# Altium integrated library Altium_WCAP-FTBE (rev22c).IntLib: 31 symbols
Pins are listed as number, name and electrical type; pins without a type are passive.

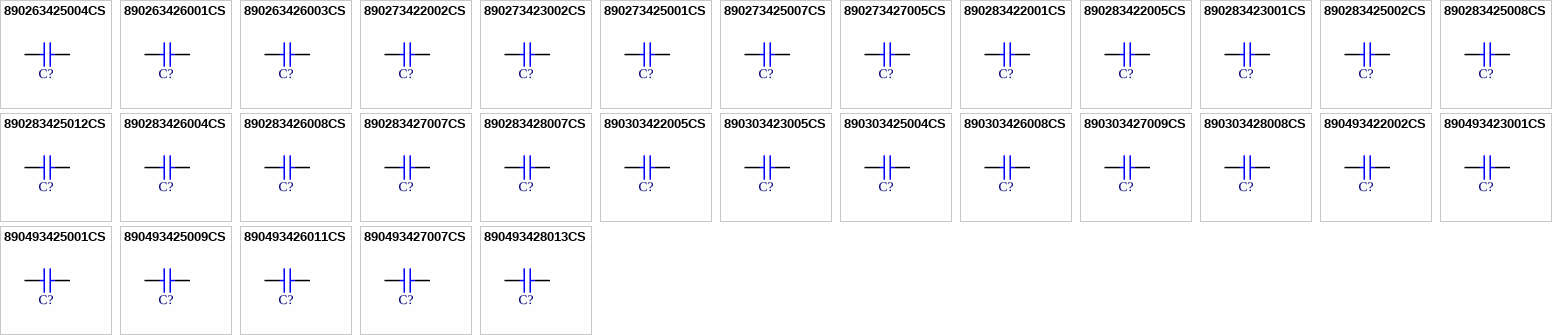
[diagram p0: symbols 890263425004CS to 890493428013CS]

## 890263425004CS
designator C?, comment 2.2µF  (value not drawn)
WCAP-FTBE Film Capacitor, THT, L18 x W8.5 x H15mm, 2.2µF, 100V; Manufacturer Part Number: 890263425004CS; Manufacturer: Wurth Elektronik; Capacitance Tolerance: +/-10%; Dissipation Factor @1kHz: 1%; Dissipation Factor @10kHz: 1.6%; Dissipation Factor @100kHz: 5%; Insulation Resistance: 3000Ω x F; Pitch: 15mm; Rate of Voltage Rise: 9V/µs; Technical Reference: MPSP015225K100DCPP45004
footprint WCAP-FTBE_L18W8.5H15
simulation model 890263425004CS_2.2uF
pins: 1, 2

## 890263426001CS
designator C?, comment 2.2µF  (value not drawn)
WCAP-FTBE Film Capacitor, THT, L26 x W6 x H15mm, 2.2µF, 100V; Manufacturer Part Number: 890263426001CS; Manufacturer: Wurth Elektronik; Capacitance Tolerance: +/-10%; Dissipation Factor @1kHz: 1%; Dissipation Factor @10kHz: 2%; Dissipation Factor @100kHz: 10%; Insulation Resistance: 3000Ω x F; Pitch: 22.5mm; Rate of Voltage Rise: 5V/µs; Technical Reference: MPSP225225K100DCPP45004
footprint WCAP-FTBE_L26W6H15
simulation model 890263426001CS_2.2uF
pins: 1, 2

## 890263426003CS
designator C?, comment 3.3µF  (value not drawn)
WCAP-FTBE Film Capacitor, THT, L26 x W7 x H16.5mm, 3.3µF, 100V; Manufacturer Part Number: 890263426003CS; Manufacturer: Wurth Elektronik; Capacitance Tolerance: +/-10%; Dissipation Factor @1kHz: 1%; Dissipation Factor @10kHz: 2.1%; Dissipation Factor @100kHz: 10%; Insulation Resistance: 3000Ω x F; Pitch: 22.5mm; Rate of Voltage Rise: 5V/µs; Technical Reference: MPSP225335K100DCPP35004
footprint WCAP-FTBE_L26W7H16.5
simulation model 890263426003CS_3.3uF
pins: 1, 2

## 890273422002CS
designator C?, comment 220nF  (value not drawn)
WCAP-FTBE Film Capacitor, THT, L10.5 x W6 x H12mm, 220nF, 250V; Manufacturer Part Number: 890273422002CS; Manufacturer: Wurth Elektronik; Capacitance Tolerance: +/-10%; Dissipation Factor @1kHz: 1%; Dissipation Factor @10kHz: 1.4%; Dissipation Factor @100kHz: 2.4%; Insulation Resistance: 9000MΩ; Pitch: 7.5mm; Rate of Voltage Rise: 38V/µs; Technical Reference: MPSP075224K250DCPP45004
footprint WCAP-FTBE_L10.5W6H12
simulation model 890273422002CS_220nF
pins: 1, 2

## 890273423002CS
designator C?, comment 220nF  (value not drawn)
WCAP-FTBE Film Capacitor, THT, L13 x W5 x H11mm, 220nF, 250V; Manufacturer Part Number: 890273423002CS; Manufacturer: Wurth Elektronik; Capacitance Tolerance: +/-10%; Dissipation Factor @1kHz: 1%; Dissipation Factor @10kHz: 1.4%; Dissipation Factor @100kHz: 3.1%; Insulation Resistance: 9000MΩ; Pitch: 10mm; Rate of Voltage Rise: 23V/µs; Technical Reference: MPSP010224K250DCPP55004
footprint WCAP-FTBE_L13W5H11
simulation model 890273423002CS_220nF
pins: 1, 2

## 890273425001CS
designator C?, comment 330nF  (value not drawn)
WCAP-FTBE Film Capacitor, THT, L18 x W5 x H11mm, 330nF, 250V; Manufacturer Part Number: 890273425001CS; Manufacturer: Wurth Elektronik; Capacitance Tolerance: +/-10%; Dissipation Factor @1kHz: 1%; Dissipation Factor @10kHz: 1.5%; Dissipation Factor @100kHz: 4%; Insulation Resistance: 9000MΩ; Pitch: 15mm; Rate of Voltage Rise: 8V/µs; Technical Reference: MPSP015334K250DCPP45004
footprint WCAP-FTBE_L18W5H11
simulation model 890273425001CS_330nF
pins: 1, 2

## 890273425007CS
designator C?, comment 1µF  (value not drawn)
WCAP-FTBE Film Capacitor, THT, L18 x W7 x H13mm, 1µF, 250V; Manufacturer Part Number: 890273425007CS; Manufacturer: Wurth Elektronik; Capacitance Tolerance: +/-10%; Dissipation Factor @1kHz: 1%; Dissipation Factor @10kHz: 1.5%; Dissipation Factor @100kHz: 4.3%; Insulation Resistance: 3000Ω x F; Pitch: 15mm; Rate of Voltage Rise: 11V/µs; Technical Reference: MPSP015105K250DCPP45004
footprint WCAP-FTBE_L18W7H13
simulation model 890273425007CS_1uF
pins: 1, 2

## 890273427005CS
designator C?, comment 4.7µF  (value not drawn)
WCAP-FTBE Film Capacitor, THT, L31 x W11 x H20mm, 4.7µF, 250V; Manufacturer Part Number: 890273427005CS; Manufacturer: Wurth Elektronik; Capacitance Tolerance: +/-10%; Dissipation Factor @1kHz: 1%; Dissipation Factor @10kHz: 2.2%; Dissipation Factor @100kHz: 11%; Insulation Resistance: 3000Ω x F; Pitch: 27.5mm; Rate of Voltage Rise: 6V/µs; Technical Reference: MPSP275475K250DCPP35004
footprint WCAP-FTBE_L31W11H20
simulation model 890273427005CS_4.7uF
pins: 1, 2

## 890283422001CS
designator C?, comment 68nF  (value not drawn)
WCAP-FTBE Film Capacitor, THT, L10.5 x W5 x H11mm, 68nF, 400V; Manufacturer Part Number: 890283422001CS; Manufacturer: Wurth Elektronik; Capacitance Tolerance: +/-10%; Dissipation Factor @1kHz: 1%; Dissipation Factor @10kHz: 1.4%; Dissipation Factor @100kHz: 2.3%; Insulation Resistance: 9000MΩ; Pitch: 7.5mm; Rate of Voltage Rise: 44V/µs; Technical Reference: MPSP075683K400DCPP45004
footprint WCAP-FTBE_L10.5W5H11
simulation model 890283422001CS_68nF
pins: 1, 2

## 890283422005CS
designator C?, comment 150nF  (value not drawn)
WCAP-FTBE Film Capacitor, THT, L10.5 x W6 x H12mm, 150nF, 400V; Manufacturer Part Number: 890283422005CS; Manufacturer: Wurth Elektronik; Capacitance Tolerance: +/-10%; Dissipation Factor @1kHz: 1%; Dissipation Factor @10kHz: 1.4%; Dissipation Factor @100kHz: 2.3%; Insulation Resistance: 9000MΩ; Pitch: 7.5mm; Rate of Voltage Rise: 46V/µs; Technical Reference: MPSP075154K400DCPP45004
footprint WCAP-FTBE_L10.5W6H12
simulation model 890283422005CS_150nF
pins: 1, 2

## 890283423001CS
designator C?, comment 100nF  (value not drawn)
WCAP-FTBE Film Capacitor, THT, L13 x W5 x H11mm, 100nF, 400V; Manufacturer Part Number: 890283423001CS; Manufacturer: Wurth Elektronik; Capacitance Tolerance: +/-10%; Dissipation Factor @1kHz: 1%; Dissipation Factor @10kHz: 1.4%; Dissipation Factor @100kHz: 2.4%; Insulation Resistance: 9000MΩ; Pitch: 10mm; Rate of Voltage Rise: 34V/µs; Technical Reference: MPSP010104K400DCPP55004
footprint WCAP-FTBE_L13W5H11
simulation model 890283423001CS_100nF
pins: 1, 2

## 890283425002CS
designator C?, comment 220nF  (value not drawn)
WCAP-FTBE Film Capacitor, THT, L18 x W5 x H11mm, 220nF, 400V; Manufacturer Part Number: 890283425002CS; Manufacturer: Wurth Elektronik; Capacitance Tolerance: +/-10%; Dissipation Factor @1kHz: 1%; Dissipation Factor @10kHz: 1.5%; Dissipation Factor @100kHz: 3.6%; Insulation Resistance: 9000MΩ; Pitch: 15mm; Rate of Voltage Rise: 12V/µs; Technical Reference: MPSP015224K400DCPP45004
footprint WCAP-FTBE_L18W5H11
simulation model 890283425002CS_220nF
pins: 1, 2

## 890283425008CS
designator C?, comment 680nF  (value not drawn)
WCAP-FTBE Film Capacitor, THT, L18 x W8.5 x H15mm, 680nF, 400V; Manufacturer Part Number: 890283425008CS; Manufacturer: Wurth Elektronik; Capacitance Tolerance: +/-10%; Dissipation Factor @1kHz: 1%; Dissipation Factor @10kHz: 1.5%; Dissipation Factor @100kHz: 3.8%; Insulation Resistance: 3000Ω x F; Pitch: 15mm; Rate of Voltage Rise: 18V/µs; Technical Reference: MPSP015684K400DCPP45004
footprint WCAP-FTBE_L18W8.5H15
simulation model 890283425008CS_680nF
pins: 1, 2

## 890283425012CS
designator C?, comment 1.5µF  (value not drawn)
WCAP-FTBE Film Capacitor, THT, L18 x W12 x H21mm, 1.5µF, 400V; Manufacturer Part Number: 890283425012CS; Manufacturer: Wurth Elektronik; Capacitance Tolerance: +/-10%; Dissipation Factor @1kHz: 1%; Dissipation Factor @10kHz: 1.5%; Dissipation Factor @100kHz: 4%; Insulation Resistance: 3000Ω x F; Pitch: 15mm; Rate of Voltage Rise: 20V/µs; Technical Reference: MPSP015155K400DCPP35004
footprint WCAP-FTBE_L18W12H21
pins: 1, 2

## 890283426004CS
designator C?, comment 470nF  (value not drawn)
WCAP-FTBE Film Capacitor, THT, L26 x W6 x H15mm, 470nF, 400V; Manufacturer Part Number: 890283426004CS; Manufacturer: Wurth Elektronik; Capacitance Tolerance: +/-10%; Dissipation Factor @1kHz: 1%; Dissipation Factor @10kHz: 1.6%; Dissipation Factor @100kHz: 4.6%; Insulation Resistance: 3000Ω x F; Pitch: 22.5mm; Rate of Voltage Rise: 11V/µs; Technical Reference: MPSP225474K400DCPP45004
footprint WCAP-FTBE_L26W6H15
simulation model 890283426004CS_470nF
pins: 1, 2

## 890283426008CS
designator C?, comment 1µF  (value not drawn)
WCAP-FTBE Film Capacitor, THT, L26 x W9 x H18mm, 1µF, 400V; Manufacturer Part Number: 890283426008CS; Manufacturer: Wurth Elektronik; Capacitance Tolerance: +/-10%; Dissipation Factor @1kHz: 1%; Dissipation Factor @10kHz: 1.6%; Dissipation Factor @100kHz: 4.8%; Insulation Resistance: 3000Ω x F; Pitch: 22.5mm; Rate of Voltage Rise: 13V/µs; Technical Reference: MPSP225105K400DCPP35004
footprint WCAP-FTBE_L26W9H18
simulation model 890283426008CS_1uF
pins: 1, 2

## 890283427007CS
designator C?, comment 3.3µF  (value not drawn)
WCAP-FTBE Film Capacitor, THT, L31 x W15 x H24.5mm, 3.3µF, 400V; Manufacturer Part Number: 890283427007CS; Manufacturer: Wurth Elektronik; Capacitance Tolerance: +/-10%; Dissipation Factor @1kHz: 1%; Dissipation Factor @10kHz: 2%; Dissipation Factor @100kHz: 9%; Insulation Resistance: 3000Ω x F; Pitch: 27.5mm; Rate of Voltage Rise: 11V/µs; Technical Reference: MPSP275335K400DCPP25004
footprint WCAP-FTBE_L31W15H24.5
simulation model 890283427007CS_3.3uF
pins: 1, 2

## 890283428007CS
designator C?, comment 6.8µF  (value not drawn)
WCAP-FTBE Film Capacitor, THT, L42 x W20.5 x H34mm, 6.8µF, 400V; Manufacturer Part Number: 890283428007CS; Manufacturer: Wurth Elektronik; Capacitance Tolerance: +/-10%; Dissipation Factor @1kHz: 1%; Dissipation Factor @10kHz: 2.3%; Dissipation Factor @100kHz: 13%; Insulation Resistance: 3000Ω x F; Pitch: 37.5mm; Rate of Voltage Rise: 9V/µs; Technical Reference: MPSP375685K400DCPP25004
footprint WCAP-FTBE_L42W20.5H34
simulation model 890283428007CS_6.8uF
pins: 1, 2

## 890303422005CS
designator C?, comment 47nF  (value not drawn)
WCAP-FTBE Film Capacitor, THT, L10.5 x W6 x H12mm, 47nF, 630V; Manufacturer Part Number: 890303422005CS; Manufacturer: Wurth Elektronik; Capacitance Tolerance: +/-10%; Dissipation Factor @1kHz: 1%; Dissipation Factor @10kHz: 1.4%; Dissipation Factor @100kHz: 2.2%; Insulation Resistance: 9000MΩ; Pitch: 7.5mm; Rate of Voltage Rise: 100V/µs; Technical Reference: MPSP075473K630DCPP45004
footprint WCAP-FTBE_L10.5W6H12
simulation model 890303422005CS_47nF
pins: 1, 2

## 890303423005CS
designator C?, comment 68nF  (value not drawn)
WCAP-FTBE Film Capacitor, THT, L13 x W5.5 x H11mm, 68nF, 630V; Manufacturer Part Number: 890303423005CS; Manufacturer: Wurth Elektronik; Capacitance Tolerance: +/-10%; Dissipation Factor @1kHz: 1%; Dissipation Factor @10kHz: 1.4%; Dissipation Factor @100kHz: 2.3%; Insulation Resistance: 9000MΩ; Pitch: 10mm; Rate of Voltage Rise: 52V/µs; Technical Reference: MPSP010683K630DCPP55004
footprint WCAP-FTBE_L13W5.5H11
simulation model 890303423005CS_68nF
pins: 1, 2

## 890303425004CS
designator C?, comment 100nF  (value not drawn)
WCAP-FTBE Film Capacitor, THT, L18 x W6 x H12mm, 100nF, 630V; Manufacturer Part Number: 890303425004CS; Manufacturer: Wurth Elektronik; Capacitance Tolerance: +/-10%; Dissipation Factor @1kHz: 1%; Dissipation Factor @10kHz: 1.4%; Dissipation Factor @100kHz: 3.2%; Insulation Resistance: 9000MΩ; Pitch: 15mm; Rate of Voltage Rise: 28V/µs; Technical Reference: MPSP015104K630DCPP45004
footprint WCAP-FTBE_L18W6H12
simulation model 890303425004CS_100nF
pins: 1, 2

## 890303426008CS
designator C?, comment 470nF  (value not drawn)
WCAP-FTBE Film Capacitor, THT, L26 x W9 x H18mm, 470nF, 630V; Manufacturer Part Number: 890303426008CS; Manufacturer: Wurth Elektronik; Capacitance Tolerance: +/-10%; Dissipation Factor @1kHz: 1%; Dissipation Factor @10kHz: 1.5%; Dissipation Factor @100kHz: 4%; Insulation Resistance: 3000Ω x F; Pitch: 22.5mm; Rate of Voltage Rise: 20V/µs; Technical Reference: MPSP225474K630DCPP35004
footprint WCAP-FTBE_L26W9H18
simulation model 890303426008CS_470nF
pins: 1, 2

## 890303427009CS
designator C?, comment 1.5µF  (value not drawn)
WCAP-FTBE Film Capacitor, THT, L31 x W15 x H24.5mm, 1.5µF, 630V; Manufacturer Part Number: 890303427009CS; Manufacturer: Wurth Elektronik; Capacitance Tolerance: +/-10%; Dissipation Factor @1kHz: 1%; Dissipation Factor @10kHz: 1.6%; Dissipation Factor @100kHz: 5.2%; Insulation Resistance: 3000Ω x F; Pitch: 27.5mm; Rate of Voltage Rise: 17V/µs; Technical Reference: MPSP275155K630DCPP25004
footprint WCAP-FTBE_L31W15H24.5
simulation model 890303427009CS_1.5uF
pins: 1, 2

## 890303428008CS
designator C?, comment 3.3µF  (value not drawn)
WCAP-FTBE Film Capacitor, THT, L42 x W17 x H30mm, 3.3µF, 630V; Manufacturer Part Number: 890303428008CS; Manufacturer: Wurth Elektronik; Capacitance Tolerance: +/-10%; Dissipation Factor @1kHz: 1%; Dissipation Factor @10kHz: 2.1%; Dissipation Factor @100kHz: 11%; Insulation Resistance: 3000Ω x F; Pitch: 37.5mm; Rate of Voltage Rise: 12V/µs; Technical Reference: MPSP375335K630DCPP25004
footprint WCAP-FTBE_L42W17H30
simulation model 890303428008CS_3.3uF
pins: 1, 2

## 890493422002CS
designator C?, comment 10nF  (value not drawn)
WCAP-FTBE Film Capacitor, THT, L10.5 x W6 x H12mm, 10nF, 1000V; Manufacturer Part Number: 890493422002CS; Manufacturer: Wurth Elektronik; Capacitance Tolerance: +/-10%; Dissipation Factor @1kHz: 1%; Dissipation Factor @10kHz: 1.4%; Dissipation Factor @100kHz: 2.2%; Insulation Resistance: 9000MΩ; Pitch: 7.5mm; Rate of Voltage Rise: 160V/µs; Technical Reference: MPSP075103KA00DCPP45004
footprint WCAP-FTBE_L10.5W6H12
simulation model 890493422002CS_10nF
pins: 1, 2

## 890493423001CS
designator C?, comment 15nF  (value not drawn)
WCAP-FTBE Film Capacitor, THT, L13 x W5 x H11mm, 15nF, 1000V; Manufacturer Part Number: 890493423001CS; Manufacturer: Wurth Elektronik; Capacitance Tolerance: +/-10%; Dissipation Factor @1kHz: 1%; Dissipation Factor @10kHz: 1.4%; Dissipation Factor @100kHz: 2.2%; Insulation Resistance: 9000MΩ; Pitch: 10mm; Rate of Voltage Rise: 83V/µs; Technical Reference: MPSP010153KA00DCPP55004
footprint WCAP-FTBE_L13W5H11
simulation model 890493423001CS_15nF
pins: 1, 2

## 890493425001CS
designator C?, comment 22nF  (value not drawn)
WCAP-FTBE Film Capacitor, THT, L18 x W5 x H11mm, 22nF, 1000V; Manufacturer Part Number: 890493425001CS; Manufacturer: Wurth Elektronik; Capacitance Tolerance: +/-10%; Dissipation Factor @1kHz: 1%; Dissipation Factor @10kHz: 1.4%; Dissipation Factor @100kHz: 2.5%; Insulation Resistance: 9000MΩ; Pitch: 15mm; Rate of Voltage Rise: 27V/µs; Technical Reference: MPSP015223KA00DCPP45004
footprint WCAP-FTBE_L18W5H11
simulation model 890493425001CS_22nF
pins: 1, 2

## 890493425009CS
designator C?, comment 100nF  (value not drawn)
WCAP-FTBE Film Capacitor, THT, L18 x W8.5 x H15mm, 100nF, 1000V; Manufacturer Part Number: 890493425009CS; Manufacturer: Wurth Elektronik; Capacitance Tolerance: +/-10%; Dissipation Factor @1kHz: 1%; Dissipation Factor @10kHz: 1.4%; Dissipation Factor @100kHz: 2.5%; Insulation Resistance: 9000MΩ; Pitch: 15mm; Rate of Voltage Rise: 44V/µs; Technical Reference: MPSP015104KA00DCPP45004
footprint WCAP-FTBE_L18W8.5H15
simulation model 890493425009CS_100nF
pins: 1, 2

## 890493426011CS
designator C?, comment 220nF  (value not drawn)
WCAP-FTBE Film Capacitor, THT, L26 x W9 x H18mm, 220nF, 1000V; Manufacturer Part Number: 890493426011CS; Manufacturer: Wurth Elektronik; Capacitance Tolerance: +/-10%; Dissipation Factor @1kHz: 1%; Dissipation Factor @10kHz: 1.5%; Dissipation Factor @100kHz: 3.6%; Insulation Resistance: 9000MΩ; Pitch: 22.5mm; Rate of Voltage Rise: 27V/µs; Technical Reference: MPSP225224KA00DCPP35004
footprint WCAP-FTBE_L26W9H18
simulation model 890493426011CS_220nF
pins: 1, 2

## 890493427007CS
designator C?, comment 470nF  (value not drawn)
WCAP-FTBE Film Capacitor, THT, L31 x W11 x H20mm, 470nF, 1000V; Manufacturer Part Number: 890493427007CS; Manufacturer: Wurth Elektronik; Capacitance Tolerance: +/-10%; Dissipation Factor @1kHz: 1%; Dissipation Factor @10kHz: 1.5%; Dissipation Factor @100kHz: 4.3%; Insulation Resistance: 3000Ω x F; Pitch: 27.5mm; Rate of Voltage Rise: 22V/µs; Technical Reference: MPSP275474KA00DCPP35004
footprint WCAP-FTBE_L31W11H20
simulation model 890493427007CS_470nF
pins: 1, 2

## 890493428013CS
designator C?, comment 4.7µF  (value not drawn)
WCAP-FTBE Film Capacitor, THT, L42 x W31 x H43mm, 4.7µF, 1000V; Manufacturer Part Number: 890493428013CS; Manufacturer: Wurth Elektronik; Capacitance Tolerance: +/-10%; Dissipation Factor @1kHz: 1%; Dissipation Factor @10kHz: 2%; Dissipation Factor @100kHz: 10%; Insulation Resistance: 3000Ω x F; Pitch: 37.5mm; Rate of Voltage Rise: 16V/µs; Technical Reference: MPSP375475KA00DCPP25004
footprint WCAP-FTBE_L42W31H43
simulation model 890493428013CS_4.7uF
pins: 1, 2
